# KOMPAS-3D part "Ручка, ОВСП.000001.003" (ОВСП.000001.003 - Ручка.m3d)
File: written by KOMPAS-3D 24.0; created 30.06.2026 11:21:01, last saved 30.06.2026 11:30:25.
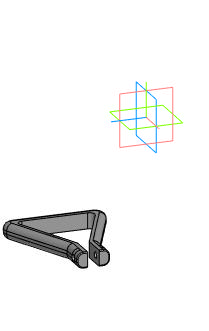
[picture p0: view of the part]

Document properties: Автор: Админ; Полное имя файла: C:\Users\Админ\Documents\ОВСП.000001.003 - Ручка.m3d

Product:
- Part/product: Ручка  | designation ОВСП.000001.003
    Масса: 0.296175

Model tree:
1. Эскиз:1  (labels: Грань.Элемент выдавливания:1.Экземпляр ( 2 ); Ребро.Элемент выдавливания:1.Экземпляр ( 2 ))
2. Элемент выдавливания:1
     Расстояние 1 = 10
3. Эскиз:2  (with: Грань.Элемент выдавливания:1, Вершина.Элемент выдавливания:1, Ребро.Элемент выдавливания:1)
4. Элемент выдавливания:2  (with: Грань.Элемент выдавливания:1)
     Расстояние 1 = -15
5. Элемент выдавливания:3  (with: Грань.Элемент выдавливания:2, Грань.Элемент выдавливания:1)
     Расстояние 1 = 25
6. Элемент выдавливания:4  (with: Ребро.Элемент выдавливания:1)
     Расстояние 2 = 38
7. Скругление:1  (with: Ребро.Элемент выдавливания:3, Ребро.Элемент выдавливания:2, Ребро.Элемент выдавливания:1)
     Радиус = 6
8. Скругление:2  (with: Ребро.Элемент выдавливания:3, Ребро.Скругление:1, Ребро.Элемент выдавливания:1)
     Радиус = 1

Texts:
  ОВСП.000001.003
  Плоскость XY.Начало координат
